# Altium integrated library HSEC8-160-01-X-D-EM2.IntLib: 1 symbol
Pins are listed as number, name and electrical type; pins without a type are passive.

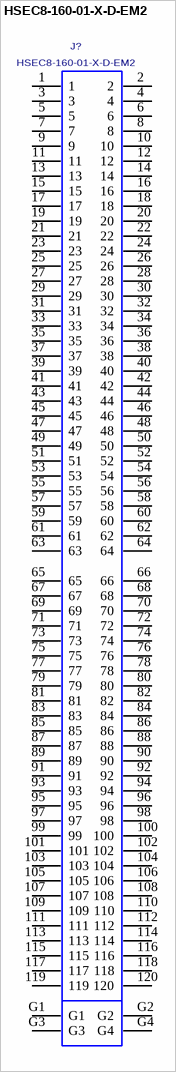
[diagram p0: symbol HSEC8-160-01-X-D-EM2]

## HSEC8-160-01-X-D-EM2
designator J?
.8mm High Speed, Dual Edge Mount, Mini-Edge Card Assembly; MANUFACTURER: SAMTEC
footprint HSEC8-160-01-X-D-EM2
pins: 1, 2, 3, 4, 5, 6, 7, 8, 9, 10, 11, 12, 13, 14, 15, 16, 17, 18, 19, 20, 21, 22, 23, 24, 25, 26, 27, 28, 29, 30, 31, 32, 33, 34, 35, 36, 37, 38, 39, 40, 41, 42, 43, 44, 45, 46, 47, 48, 49, 50, 51, 52, 53, 54, 55, 56, 57, 58, 59, 60, 61, 62, 63, 64, 65, 66, 67, 68, 69, 70, 71, 72, 73, 74, 75, 76, 77, 78, 79, 80, 81, 82, 83, 84, 85, 86, 87, 88, 89, 90, 91, 92, 93, 94, 95, 96, 97, 98, 99, 100, 101, 102, 103, 104, 105, 106, 107, 108, 109, 110, 111, 112, 113, 114, 115, 116, 117, 118, 119, 120, G1, G2, G3, G4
